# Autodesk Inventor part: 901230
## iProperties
Created: 2007-10
Part Number: 901230
Document SubType Name: Modeling
Designer: TT
Density: 1.06 g/cm^3
Mass: 6.30275 g
Surface Area: 103.939 cm^2
Volume: 5.94599 cm^3
Material: ABS Plastic
Description: R34 MOTOR CONNECTOR
Component Category: Electrical
Author: TT
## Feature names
1. Extrusion1
2. Extrusion2
3. Extrusion3
4. Extrusion4
5. Extrusion5
6. Extrusion6
7. Fillet1
8. Fillet2
9. Fillet3
10. Chamfer1
11. Extrusion7
12. Rectangular Pattern1
13. Extrusion8
14. Rectangular Pattern2
15. Extrusion9
16. Extrusion10
17. Extrusion11
18. Chamfer2
19. Chamfer3
20. Fillet5
21. Fillet6
22. Extrusion12
23. Fillet7
24. Fillet8
